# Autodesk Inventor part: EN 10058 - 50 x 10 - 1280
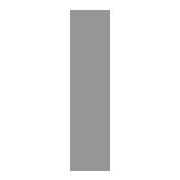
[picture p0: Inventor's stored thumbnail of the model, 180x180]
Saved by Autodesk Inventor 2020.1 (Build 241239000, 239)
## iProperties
IsCustomPart: 1
_CCFamilyMember: 59
_CCFamilyDisplayName: DIN EN 10058 - Warmgewalzte Flachstahlprofile - Mehrzweck
_FrameMemberDoc: Frame Member File
_Version: 15.0.0
_GetPNFromCC: 1
Created: 2019-01
Part Number: EN 10058 - 50 x 10 - 1280
Material: Stahl, weich
Description: Warmgewalzte Flachstahlprofile - Mehrzweck
Document SubType Name: Modeling
Standard: DIN
Designer: lutzd
Standard Revision: 2004
Standards Organization: DIN
Language: de-DE
Size Designation: 50 x 10
Categories: <MemberInstance><Categories><Category DisplayName="Profile" InternalName="089c4875-fa83-4c05-b084-43b9cc11f5ed" Mnemonic="GRDR"><CategoryParameter DisplayName="
Stock Number: 50 x 10
Mass: 4980.75 g
Surface Area: 1561.29 cm^2
Volume: 634.49 cm^3
Density: 7.85 g/cm^3
Appearance: Halbpoliert
G_L: 1280,000 mm
G_W: 10,000 mm
G_H: 50,000 mm
DocNumber: ADSK-014141
Folder: .
Dimensions: 10x50x1280 mm
Mass: 4,981 kg
Title: Profil-Bauteil
Author: lutzd
Revision Number: -
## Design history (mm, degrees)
node "Startebene"
node "Endebene"
sketch "Skizze"
  geometry: L1 (5, -25)-(-5, -25); L2 (-5, -25)-(-5, 25); L3 (-5, 25)-(5, 25); L4 (5, 25)-(5, -25); L5 (-6, 0)-(8, 0); L6 (0, -30)-(0, 40); L7 (0, 54)-(0, -44) reference; L8 (-9.2, 0)-(13.2, 0) reference
  constraints: 12 end point, 2 collinear, 2 parallel, 1 horizontal, 1 perpendicular
  dimensions: "d0" = 50 distance between parallel lines of L3 L1 (= G_W); "d1" = 10 distance between parallel lines of L4 L2 (= G_H); "d4" = 5 distance between parallel lines of L6 L4 (= 0.5 x d1); "d5" = 25 distance between parallel lines of L5 L3 (= 0.5 x d0)
extrude "Körper" new body sketch "Skizze" stored distance "d2" = 1280 (= G_L); taper "d3" = 0 deg
node "Driven Length"
  sketch "Sketch3"
    geometry: L1 (0, 0)-(10, 0) reference
    constraints: 2 end point, 1 horizontal
  workplane "Work Plane3"
  sketch "Sketch4"
    geometry: L1 (-2, 0)-(12, 0) reference; L2 (-2, 1280)-(12, 1280) reference
    dimensions: "d9" = 1280 distance between parallel lines of L1 L2 (derived)
sketch "Skizze5"
  geometry: L1 (1280, -50)-(1280, 0) reference; L2 (0, -50)-(0, 0) reference; 12 further points
  constraints: 1 midpoint, 13 other
  dimensions: "d10" = 77 distance from line of L1 point (1203, -25); "d11" = 125 distance of point (1203, -25) point (1078, -25); "d12" = 125 distance of point (953, -25) point (1078, -25) (= d11); "d13" = 125 distance of point (828, -25) point (953, -25) (= d11); "d14" = 125 distance of point (828, -25) point (703, -25) (= d11); "d15" = 125 distance of point (578, -25) point (703, -25) (= d11); "d16" = 125 distance of point (578, -25) point (453, -25) (= d11); "d17" = 125 distance of point (328, -25) point (453, -25) (= d11); "d18" = 125 distance of point (203, -25) point (328, -25) (= d11); "d19" = 125 distance of point (203, -25) point (78, -25) (= d11)
hole "Bohrung1" sketch "Skizze5" at (1203, -25), (1078, -25), (328, -25), (953, -25), (828, -25), (703, -25), (578, -25), (453, -25), (203, -25), (78, -25) diameter "d20" = 8.376; stored, may be unused: countersink angle "d24" = 90 deg, drill point angle "d26" = 0 deg; dims "d21" = 20, "d22" = 4, "d23" = 2, "d25" = 27.3
body "Solid1"
other parameters: "G_W" = 50 [user parameter; used in 1 equation term], "G_H" = 10 [user parameter; used in 1 equation term], "G_L" = 1280 (= d9) [user parameter; used in 1 equation term], "G_OFFSET_START" = 0 [user parameter; used in 1 equation term], "G_OFFSET_END" = 0 [user parameter; used in 1 equation term], "d6" = 0 (computed from G_OFFSET_START), "d8" = 90 deg, "MAS" = 0.393 [user parameter]
